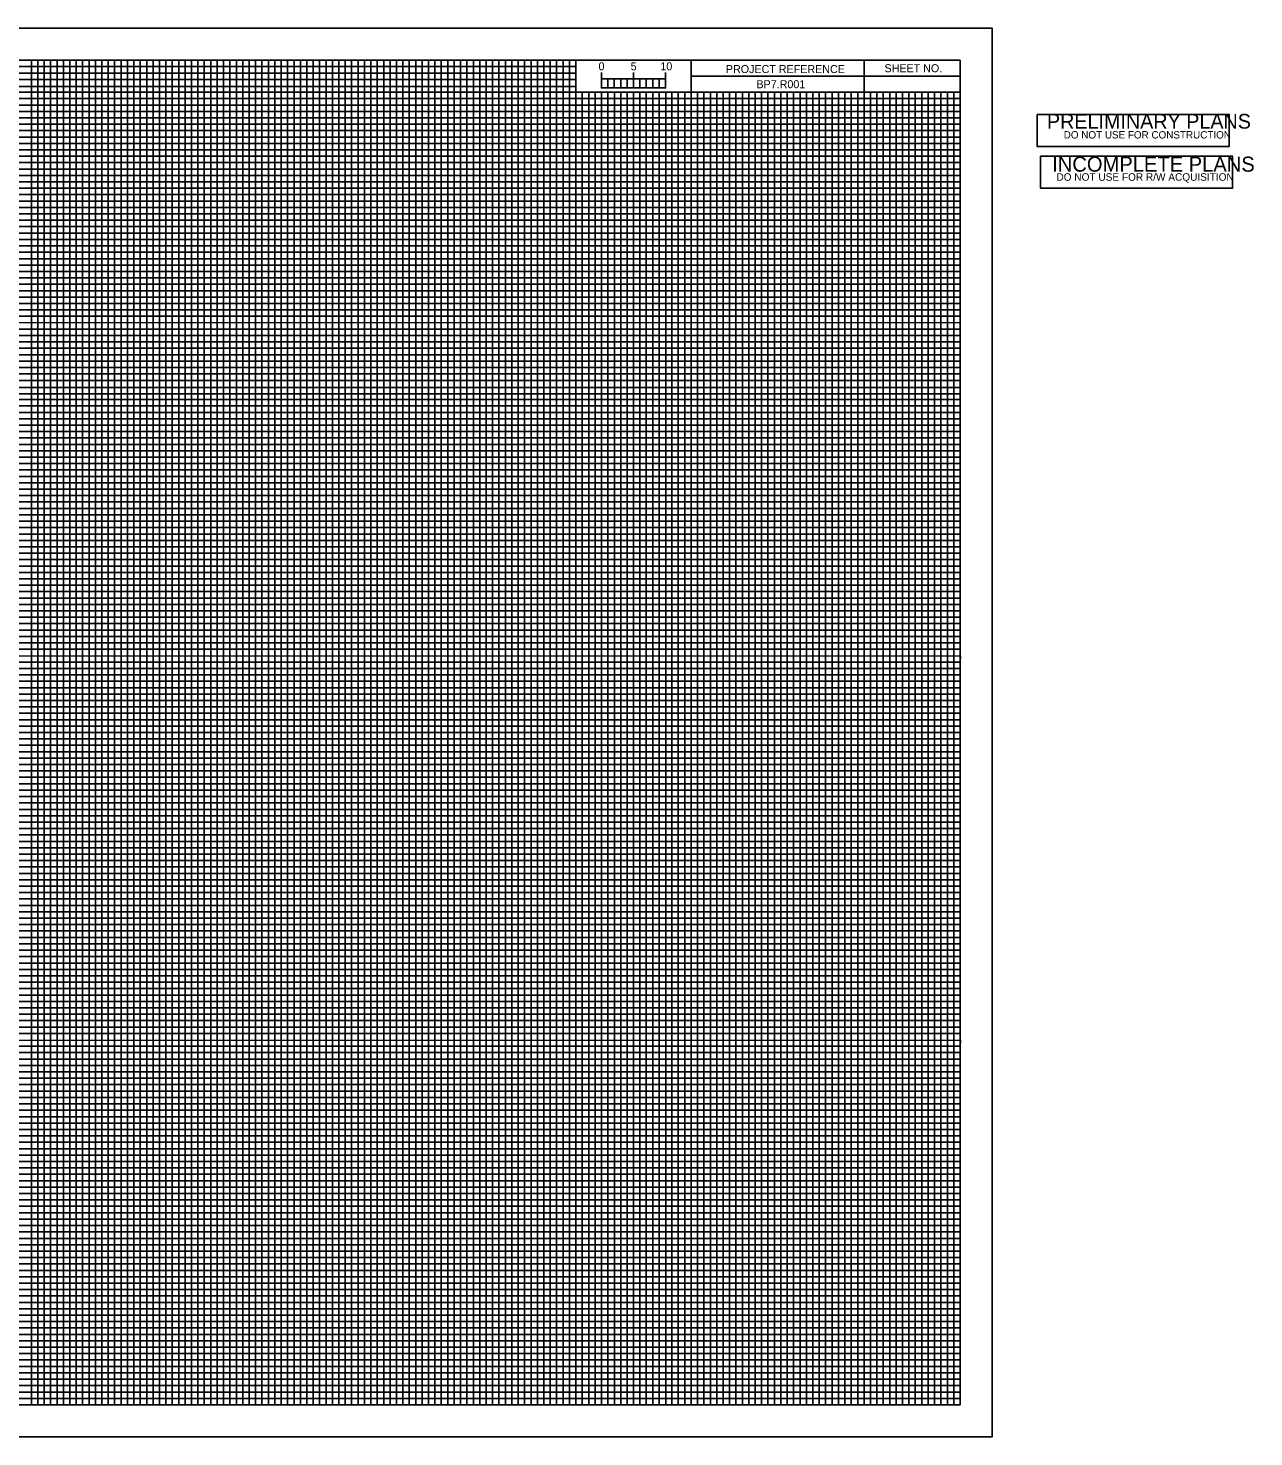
# Model space of a CAD drawing. Extents: x -1.5 to 36.6, y -0.5 to 21.5.
# Drawn here: x 17.45 to 36.58, y -0.5 to 21.5 of the extents above; entities that cross this region are included whole.
import ezdxf

# ---------------------------------------------------------------- set-up
doc = ezdxf.new("R2010")
doc.units = 0
for name, color, linetype in [('Old_Level_1', 7, 'Continuous'), ('Old_Level_18', 7, 'Continuous'), ('Old_Level_24', 7, 'Continuous'), ('Old_Level_38', 7, 'Continuous'), ('Old_Level_40', 7, 'Continuous'), ('Old_Level_41', 7, 'Continuous'), ('Old_Level_42', 7, 'Continuous'), ('Old_Level_43', 7, 'Continuous'), ('Old_Level_44', 7, 'Continuous'), ('Old_Level_62', 7, 'Continuous'), ('Old_Level_63', 7, 'Continuous')]:
    doc.layers.add(name, color=color, linetype=linetype)

msp = doc.modelspace()

# ---------------------------------------------------------------- linework, layer by layer
at = {"layer": 'Old_Level_1'}
msp.add_lwpolyline([(33.254, 19), (33.254, 19.5), (36.254, 19.5), (36.254, 19)], close=True, dxfattribs=at)
at = {"layer": 'Old_Level_18'}
msp.add_lwpolyline([(32, 21), (0, 21), (0, 0), (32, 0)], close=True, dxfattribs=at)
at = {"layer": 'Old_Level_24'}
msp.add_lwpolyline([(33.201, 20.152), (36.201, 20.152), (36.201, 19.652), (33.201, 19.652)], close=True, dxfattribs=at)
at = {"layer": 'Old_Level_38'}
for p, q in [((26.4, 20.567), (26.4, 20.808)), ((26.4, 20.708), (26.4, 20.808)), ((26.9, 20.567), (26.9, 20.808)), ((27.4, 20.567), (27.4, 20.808)), ((27.4, 20.708), (27.4, 20.808))]:
    msp.add_line(p, q, dxfattribs=at)
for points in [[(27.4, 20.708), (26.4, 20.708), (26.4, 20.567), (27.4, 20.567)], [(26.4, 20.708), (26.5, 20.708), (26.5, 20.567), (26.4, 20.567)], [(26.6, 20.708), (26.7, 20.708), (26.7, 20.567), (26.6, 20.567)], [(26.8, 20.708), (26.9, 20.708), (26.9, 20.567), (26.8, 20.567)], [(27, 20.708), (27.1, 20.708), (27.1, 20.567), (27, 20.567)], [(27.2, 20.708), (27.3, 20.708), (27.3, 20.567), (27.2, 20.567)]]:
    msp.add_lwpolyline(points, close=True, dxfattribs=at)
at = {"layer": 'Old_Level_40'}
for p, q in [((30.5, 20.5), (30.5, 21)), ((30.5, 21), (30.5, 20.5)), ((27.8, 20.749), (27.8, 20.499)), ((32, 20.749), (27.8, 20.749)), ((32, 20.749), (28, 20.749)), ((26, 20.5), (32, 20.5))]:
    msp.add_line(p, q, dxfattribs=at)
for points in [[(27.8, 21), (26, 21), (26, 20.5), (27.8, 20.5)], [(32, 21), (27.8, 21), (27.8, 20.5), (32, 20.5)]]:
    msp.add_lwpolyline(points, close=True, dxfattribs=at)
at = {"layer": 'Old_Level_41'}
for p, q in [((19, 21), (18, 21)), ((18, 21), (18, 0)), ((19, 0), (19, 21)), ((21, 21), (20, 21)), ((20, 21), (20, 0)), ((21, 0), (21, 21)), ((23, 21), (22, 21)), ((22, 21), (22, 0)), ((23, 0), (23, 21)), ((25, 21), (24, 21)), ((24, 21), (24, 0)), ((25, 0), (25, 21)), ((26, 21), (26, 20.503)), ((26, 20.5), (26, 0)), ((27, 0), (27, 20.5)), ((28, 20.5), (28, 0)), ((29, 0), (29, 20.5)), ((30, 20.5), (30, 0)), ((31, 0), (31, 20.5)), ((18, 0), (17, 0)), ((20, 0), (19, 0)), ((22, 0), (21, 0)), ((24, 0), (23, 0)), ((26, 0), (25, 0)), ((28, 0), (27, 0)), ((30, 0), (29, 0)), ((32, 0), (31, 0)), ((32, 0), (32, 0))]:
    msp.add_line(p, q, dxfattribs=at)
for points in [[(0, 20), (32, 20), (32, 19), (0, 19)], [(0, 18), (32, 18), (32, 17), (0, 17)], [(0, 16), (32, 16), (32, 15), (0, 15)], [(0, 14), (32, 14), (32, 13), (0, 13)], [(0, 12), (32, 12), (32, 11), (0, 11)], [(0, 10), (32, 10), (32, 9), (0, 9)], [(0, 8), (32, 8), (32, 7), (0, 7)], [(0, 6), (32, 6), (32, 5), (0, 5)], [(0, 4), (32, 4), (32, 3), (0, 3)], [(0, 2), (32, 2), (32, 1), (0, 1)]]:
    msp.add_lwpolyline(points, dxfattribs=at)
at = {"layer": 'Old_Level_42'}
for points in [[(16.5, 0), (17.5, 0), (17.5, 21), (18.5, 21), (18.5, 0), (19.5, 0), (19.5, 21), (20.5, 21), (20.5, 0), (21.5, 0), (21.5, 21), (22.5, 21), (22.5, 0), (23.5, 0), (23.5, 21), (24.5, 21), (24.5, 0), (25.5, 0), (25.5, 21), (25.993, 21), (26, 21), (26, 20.503)], [(0, 20.5), (26, 20.5)], [(26, 20.503), (26, 20.5)], [(26.499, 20.5), (26.499, 0), (27.5, 0), (27.5, 20.5)], [(28.5, 20.5), (28.5, 0), (29.5, 0), (29.5, 20.5)], [(30.5, 20.5), (30.5, 0), (31.5, 0), (31.5, 20.5)], [(0, 18.5), (32, 18.5), (32, 19.5), (0, 19.5)], [(0, 16.5), (32, 16.5), (32, 17.5), (0, 17.5)], [(0, 14.5), (32, 14.5), (32, 15.5), (0, 15.5)], [(0, 12.5), (32, 12.5), (32, 13.5), (0, 13.5)], [(0, 10.5), (32, 10.5), (32, 11.5), (0, 11.5)], [(0, 8.5), (32, 8.5), (32, 9.5), (0, 9.5)], [(0, 6.5), (32, 6.5), (32, 7.5), (0, 7.5)], [(0, 4.5), (32, 4.5), (32, 5.5), (0, 5.5)], [(0, 2.5), (32, 2.5), (32, 3.5), (0, 3.5)], [(0, 0.5), (32, 0.5), (32, 1.5), (0, 1.5)]]:
    msp.add_lwpolyline(points, dxfattribs=at)
at = {"layer": 'Old_Level_43'}
for p, q in [((0, 20.9), (26, 20.9)), ((26, 20.798), (0, 20.798)), ((0, 20.7), (26, 20.7)), ((26, 20.9), (26, 20.798)), ((26, 20.7), (26, 20.589)), ((26, 20.589), (0, 20.589)), ((26.601, 20.5), (26.601, 0)), ((26.7, 0), (26.7, 20.5)), ((26.8, 20.5), (26.8, 0)), ((26.9, 0), (26.9, 20.5)), ((0, 20.4), (32, 20.4)), ((26.601, 0), (26.5, 0)), ((26.8, 0), (26.7, 0))]:
    msp.add_line(p, q, dxfattribs=at)
for points in [[(0, 20.3), (32, 20.3)], [(32, 20.25), (32, 20.2), (0, 20.2)], [(0, 20.1), (32, 20.1), (32, 19.9), (0, 19.9)], [(0, 19.8), (32, 19.8), (32, 19.7), (0, 19.698)], [(0, 19.6), (32, 19.6), (32, 19.4), (0, 19.4)], [(0, 19.3), (32, 19.3), (32, 19.2), (0, 19.2)], [(0, 19.1), (32, 19.1), (32, 18.9), (0, 18.9)], [(0, 18.8), (32, 18.8), (32, 18.7), (0, 18.7)], [(0, 18.6), (32, 18.6), (32, 18.4), (0, 18.4)], [(0, 18.3), (32, 18.3), (32, 18.2), (0, 18.2)], [(0, 18.1), (32, 18.1), (32, 17.9), (0, 17.9)], [(0, 17.8), (32, 17.8), (32, 17.7), (0, 17.7)], [(0, 17.6), (32, 17.6), (32, 17.395), (32, 17.3), (32, 17.2), (0, 17.2)], [(0, 17.4), (32, 17.4), (32, 17.3), (0, 17.3)], [(0, 17.1), (32, 17.1), (32, 16.9), (0, 16.903)], [(0, 16.903), (32, 16.9), (32, 16.8), (0, 16.8)], [(0, 16.7), (32, 16.7), (32, 16.6), (0, 16.6)], [(0, 16.4), (32, 16.4), (32, 16.3), (0, 16.3)], [(0, 16.2), (32, 16.2), (32, 16.1), (0, 16.1)], [(-0.007, 15.889), (32, 15.889), (32, 15.788), (-0.007, 15.788)], [(0, 15.7), (32, 15.7), (32, 15.6), (0, 15.6)], [(0, 15.4), (32, 15.4), (32, 15.3), (0, 15.3)], [(0, 15.2), (32, 15.2), (32, 15.1), (0, 15.1)], [(0, 14.9), (32, 14.9), (32, 14.8), (0, 14.8)], [(0, 14.7), (32, 14.7), (32, 14.6), (0, 14.6)], [(0, 14.4), (32, 14.4), (32, 14.3), (0, 14.3)], [(0, 14.2), (32, 14.2), (32, 14.1), (0, 14.1)], [(0, 13.9), (32, 13.9), (31.999, 13.798), (0, 13.8)], [(0, 13.7), (32, 13.7), (32, 13.6), (0, 13.6)], [(0, 13.4), (32, 13.4), (32, 13.3), (0, 13.3)], [(0, 13.2), (32, 13.2), (32, 13.1), (0, 13.1)], [(0, 12.9), (32, 12.9), (32, 12.8), (0, 12.8)], [(0, 12.7), (32, 12.7), (32, 12.6), (0, 12.6)], [(0, 12.4), (32, 12.4), (32, 12.3), (0, 12.3)], [(0, 12.2), (32, 12.2), (32, 12.1), (0, 12.1)], [(0, 11.9), (32, 11.9), (32, 11.8), (0, 11.8)], [(0, 11.699), (32.007, 11.691), (32, 11.6), (0, 11.6)], [(0, 11.4), (32, 11.4), (32, 11.3), (0, 11.3)], [(0, 11.2), (32, 11.2), (32, 11.1), (0, 11.1)], [(0, 10.9), (32, 10.9), (32, 10.8), (0, 10.8)], [(0, 10.7), (32, 10.7), (32, 10.6), (0, 10.6)], [(0, 10.4), (32, 10.4), (32, 10.3), (0, 10.3)], [(0, 10.2), (32, 10.2), (32, 10.1), (0, 10.1)], [(0, 9.9), (32, 9.9), (32, 9.8), (0, 9.8)], [(0, 9.7), (32, 9.7), (32, 9.6), (0, 9.6)], [(0, 9.4), (32, 9.4), (32, 9.3), (0, 9.3)], [(0, 9.2), (32, 9.2), (32, 9.1), (0, 9.1)], [(0, 8.9), (32, 8.9), (32, 8.8), (0, 8.8)], [(0, 8.7), (32, 8.7), (32, 8.6), (0, 8.6)], [(0, 8.4), (32, 8.4), (32, 8.3), (0, 8.3)], [(0, 8.2), (32, 8.2), (32, 8.1), (0, 8.1)], [(0, 7.9), (32, 7.9), (31.999, 7.798), (0, 7.8)], [(0, 7.7), (32, 7.7), (32, 7.6), (0, 7.6)], [(0, 7.4), (32, 7.4), (32, 7.3), (0, 7.3)], [(0, 7.2), (32, 7.2), (32, 7.1), (0, 7.1)], [(0, 6.9), (32, 6.9), (32, 6.8), (0, 6.8)], [(0, 6.7), (32, 6.7), (32, 6.6), (0, 6.6)], [(0, 6.4), (32, 6.4), (32, 6.3), (0, 6.3)], [(0, 6.2), (32, 6.2), (32, 6.1), (0, 6.1)], [(0, 5.9), (32, 5.9), (32, 5.8), (0, 5.8)], [(0, 5.699), (32.007, 5.691), (32, 5.6), (0, 5.6)], [(0, 5.4), (32, 5.4), (32, 5.3), (0, 5.3)], [(0, 5.2), (32, 5.2), (32, 5.1), (0, 5.1)], [(0, 4.9), (32, 4.9), (32, 4.8), (0, 4.8)], [(0, 4.7), (32, 4.7), (32, 4.6), (0, 4.6)], [(0, 4.4), (32, 4.4), (32, 4.3), (0, 4.3)], [(0, 4.2), (32, 4.2), (32, 4.1), (0, 4.1)], [(0, 3.9), (32, 3.9), (32, 3.8), (0, 3.8)], [(0, 3.7), (32, 3.7), (32, 3.6), (0, 3.6)], [(0, 3.4), (32, 3.4), (32, 3.3), (0, 3.3)], [(0, 3.2), (32, 3.2), (32, 3.1), (0, 3.1)], [(0, 2.9), (32, 2.9), (32, 2.8), (0, 2.8)], [(0, 2.7), (32, 2.7), (32, 2.6), (0, 2.6)], [(0, 2.4), (32, 2.4), (32, 2.3), (0, 2.3)], [(0, 2.2), (32, 2.2), (32, 2.1), (0, 2.1)], [(0, 1.9), (32, 1.9), (32, 1.8), (0, 1.8)], [(0, 1.7), (32, 1.7), (32, 1.6), (0, 1.6)], [(0, 1.4), (32, 1.4), (32, 1.3), (0, 1.3)], [(0, 1.2), (32, 1.2), (32, 1.1), (0, 1.1)], [(0, 0.9), (32, 0.9), (32, 0.8), (0, 0.8)], [(0, 0.7), (32, 0.7), (32, 0.6), (0, 0.6)], [(0, 0.4), (32, 0.4), (32, 0.3), (0, 0.3)], [(0, 0.2), (32, 0.2), (32, 0.1), (0, 0.1)]]:
    msp.add_lwpolyline(points, dxfattribs=at)
at = {"layer": 'Old_Level_44'}
for points in [[(17.5, 0), (17.6, 0), (17.6, 21), (17.7, 21), (17.7, 0)], [(17.7, 0), (17.8, 0), (17.8, 21), (17.9, 21), (17.9, 0)], [(18, 0), (18.1, 0), (18.1, 21), (18.2, 21), (18.2, 0)], [(18.2, 0), (18.3, 0), (18.3, 21), (18.4, 21), (18.4, 0)], [(18.5, 0), (18.6, 0), (18.6, 21), (18.7, 21), (18.7, 0)], [(18.7, 0), (18.8, 0), (18.8, 21), (18.9, 21), (18.9, 0)], [(19, 0), (19.1, 0), (19.1, 21), (19.2, 21), (19.2, 0)], [(19.2, 0), (19.3, 0), (19.3, 21), (19.4, 21), (19.4, 0)], [(19.5, 0), (19.6, 0), (19.6, 21), (19.7, 21), (19.7, 0)], [(19.7, 0), (19.8, 0), (19.8, 21), (19.9, 21), (19.9, 0)], [(20, 0), (20.1, 0), (20.1, 21), (20.2, 21), (20.2, 0)], [(20.2, 0), (20.3, 0), (20.3, 21), (20.4, 21), (20.4, 0)], [(20.5, 0), (20.6, 0), (20.6, 21), (20.7, 21), (20.7, 0)], [(20.7, 0), (20.8, 0), (20.8, 21), (20.9, 21), (20.9, 0)], [(21, 0), (21.1, 0), (21.1, 21), (21.2, 21), (21.2, 0)], [(21.2, 0), (21.3, 0), (21.3, 21), (21.4, 21), (21.4, 0)], [(21.5, 0), (21.6, 0), (21.6, 21), (21.7, 21), (21.7, 0)], [(21.7, 0), (21.8, 0), (21.8, 21), (21.9, 21), (21.9, 0)], [(22, 0), (22.1, 0), (22.1, 21), (22.2, 21), (22.2, 0)], [(22.2, 0), (22.3, 0), (22.3, 21), (22.4, 21), (22.4, 0)], [(22.5, 0), (22.6, 0), (22.6, 21), (22.7, 21), (22.7, 0)], [(22.7, 0), (22.8, 0), (22.8, 21), (22.9, 21), (22.9, 0)], [(23, 0), (23.1, 0), (23.1, 21), (23.2, 21), (23.2, 0)], [(23.2, 0), (23.3, 0), (23.3, 21), (23.4, 21), (23.4, 0)], [(23.5, 0), (23.6, 0), (23.6, 21), (23.7, 21), (23.7, 0)], [(23.7, 0), (23.8, 0), (23.8, 21), (23.9, 21), (23.9, 0)], [(24, 0), (24.1, 0), (24.1, 21), (24.2, 21), (24.2, 0)], [(24.2, 0), (24.3, 0), (24.3, 21), (24.4, 21), (24.4, 0)], [(24.5, 0), (24.6, 0), (24.6, 21), (24.7, 21), (24.7, 0)], [(24.7, 0), (24.8, 0), (24.8, 21), (24.9, 21), (24.9, 0)], [(25, 0), (25.1, 0), (25.1, 21), (25.2, 21), (25.2, 0)], [(25.2, 0), (25.3, 0), (25.3, 21), (25.4, 21), (25.4, 0)], [(25.5, 0), (25.6, 0), (25.6, 21), (25.7, 21), (25.7, 0)], [(25.7, 0), (25.8, 0), (25.8, 21), (25.9, 21), (25.9, 0)], [(26, 0), (26.1, 0), (26.1, 20.5)], [(26.2, 0), (26.3, 0), (26.3, 20.5)], [(26.202, 20.5), (26.202, 0)], [(26.399, 20.5), (26.399, 0)], [(27, 0), (27.098, 0), (27.098, 20.5)], [(27.2, 20.5), (27.2, 0)], [(27.2, 0), (27.3, 0), (27.3, 20.5)], [(27.405, 20.5), (27.405, 0)], [(27.5, 0), (27.6, 0), (27.6, 20.5)], [(27.7, 20.5), (27.7, 0)], [(27.7, 0), (27.8, 0), (27.8, 20.5)], [(27.9, 20.5), (27.9, 0)], [(28, 0), (28.1, 0), (28.1, 20.5)], [(28.2, 20.5), (28.2, 0)], [(28.2, 0), (28.3, 0), (28.3, 20.5)], [(28.4, 20.5), (28.4, 0)], [(28.5, 0), (28.6, 0), (28.6, 20.5)], [(28.7, 20.5), (28.7, 0)], [(28.7, 0), (28.8, 0), (28.8, 20.5)], [(28.9, 20.5), (28.9, 0)], [(29, 0), (29.1, 0), (29.1, 20.5)], [(29.2, 20.5), (29.2, 0)], [(29.2, 0), (29.3, 0), (29.3, 20.5)], [(29.4, 20.5), (29.4, 0)], [(29.5, 0), (29.6, 0), (29.6, 20.5)], [(29.7, 20.5), (29.7, 0)], [(29.7, 0), (29.8, 0), (29.8, 20.5)], [(29.9, 20.5), (29.9, 0)], [(30, 0), (30.1, 0), (30.1, 20.5)], [(30.2, 20.5), (30.2, 0)], [(30.2, 0), (30.3, 0), (30.3, 20.5)], [(30.4, 20.5), (30.4, 0)], [(30.5, 0), (30.6, 0), (30.6, 20.5)], [(30.7, 20.5), (30.7, 0)], [(30.7, 0), (30.8, 0), (30.8, 20.5)], [(30.9, 20.5), (30.9, 0)], [(31, 0), (31.1, 0), (31.1, 20.5)], [(31.2, 20.5), (31.2, 0)], [(31.2, 0), (31.3, 0), (31.3, 20.5)], [(31.4, 20.5), (31.4, 0)], [(31.5, 0), (31.6, 0), (31.6, 20.5)], [(31.7, 20.5), (31.7, 0)], [(31.7, 0), (31.8, 0), (31.8, 20.5)], [(31.9, 20.5), (31.9, 0)]]:
    msp.add_lwpolyline(points, dxfattribs=at)
at = {"layer": 'Old_Level_62'}
msp.add_lwpolyline([(-1, 21), (32, 21), (32, 0), (-1, 0)], close=True, dxfattribs=at)
at = {"layer": 'Old_Level_63'}
msp.add_lwpolyline([(-1.5, -0.5), (32.5, -0.5), (32.5, 21.5), (-1.5, 21.5)], close=True, dxfattribs=at)

# ---------------------------------------------------------------- texts
at = {"layer": 'Old_Level_1'}
for s, height, p in [('INCOMPLETE PLANS', 0.2351, (33.437, 19.259)), ('DO NOT USE FOR R/W ACQUISITION', 0.11755, (33.503, 19.117))]:
    msp.add_text(s, height=height, dxfattribs=at).set_placement(p)
at = {"layer": 'Old_Level_24'}
for s, height, p in [('PRELIMINARY PLANS', 0.2304, (33.355, 19.931)), ('DO NOT USE FOR CONSTRUCTION', 0.1152, (33.617, 19.777))]:
    msp.add_text(s, height=height, dxfattribs=at).set_placement(p)
at = {"layer": 'Old_Level_38'}
for s, p in [('0', (26.354, 20.842)), ('5', (26.856, 20.842)), ('10', (27.32, 20.842))]:
    msp.add_text(s, height=0.125, dxfattribs=at).set_placement(p)
at = {"layer": 'Old_Level_40'}
for s, p in [('PROJECT REFERENCE', (28.343, 20.799)), ('SHEET NO.', (30.819, 20.812)), ('BP7.R001', (28.82, 20.562))]:
    msp.add_text(s, height=0.125, dxfattribs=at).set_placement(p)

doc.saveas('drawing.dxf')
